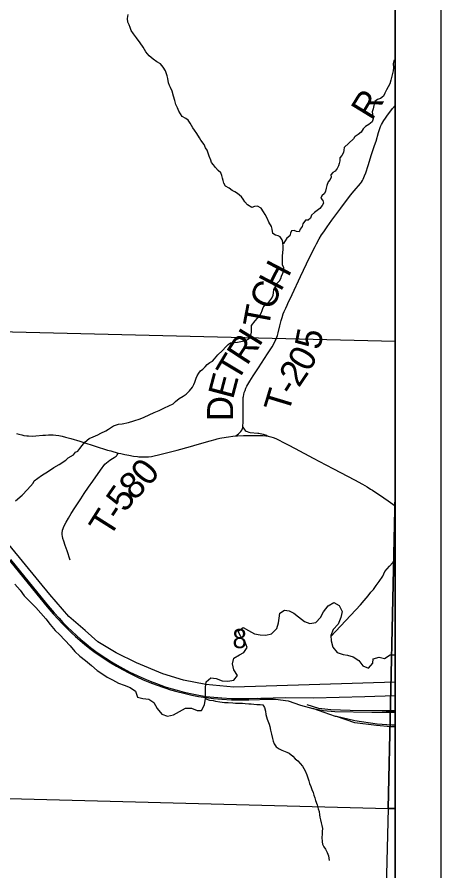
# Model space of a CAD drawing. Extents: x -19.9 to 41.9, y 0 to 32.3.
# Drawn here: x 8.077 to 9, y 15.733 to 17.59 of the extents above; entities that cross this region are included whole.
import ezdxf

# ---------------------------------------------------------------- set-up
doc = ezdxf.new("R2010")
doc.units = 0
for name, color, linetype in [('GM_X_Corporation', 7, 'Continuous'), ('GM_X_Major_River', 7, 'Continuous'), ('GM_X_Minor_River', 7, 'Continuous'), ('GM_X_Rail_Line', 7, 'Continuous'), ('GM_X_Section_Text', 7, 'Continuous'), ('GM_X_State_Route', 7, 'Continuous'), ('GM_X_Township_Road', 7, 'Continuous'), ('GM_X_Township_Road_Text', 7, 'Continuous'), ('SH_Data', 7, 'Continuous')]:
    doc.layers.add(name, color=color, linetype=linetype)

msp = doc.modelspace()

# ---------------------------------------------------------------- linework, layer by layer
at = {"layer": 'GM_X_Corporation'}
for points in [[(2.1, 17.918), (2.1, 14.1), (8.9, 14.1), (8.9, 17.8974), (7.9072, 17.9171), (7.5529, 17.9242), (7.3858, 17.9277), (6.9468, 17.937), (6.7, 17.9422), (6.3069, 17.9505), (6.2497, 17.9517), (6.2397, 17.9517), (5.9048, 17.9534), (5.761, 17.9543), (5.4954, 17.9559), (5.0257, 17.9637), (5.0192, 17.8403), (4.9169, 17.8392), (4.2613, 17.8672), (3.984, 17.879), (3.7505, 17.884), (2.973, 17.9007), (2.4715, 17.9106)], [(7.8246, 14.1), (8.9, 14.1), (8.9, 17.8974), (7.9072, 17.9171), (7.9012, 17.4524), (7.8776, 16.5173), (7.8702, 16.1679), (7.854, 15.4058), (7.8518, 15.3043)], [(8.9, 16.5515), (8.9, 16.8843), (7.8883, 16.9088), (7.8659, 15.8953), (8.8854, 15.8688)], [(8.9, 15.8686), (8.9, 16.5515), (8.8854, 15.8688)], [(8.8854, 15.8688), (8.8595, 14.8618), (7.8436, 14.8739), (7.8659, 15.8953)], [(8.9, 14.861), (8.9, 15.8686), (8.8854, 15.8688), (8.8595, 14.8618)]]:
    msp.add_lwpolyline(points, close=True, dxfattribs=at)
at = {"layer": 'GM_X_Major_River'}
for points in [[(8.0725, 16.3563), (8.0837, 16.3435), (8.093, 16.3311), (8.1057, 16.3184), (8.118, 16.306), (8.1291, 16.2933), (8.1399, 16.2809), (8.1496, 16.2692), (8.16, 16.2561), (8.1696, 16.2471), (8.1815, 16.2351), (8.1927, 16.2227), (8.2031, 16.21), (8.2142, 16.2002), (8.2261, 16.1909), (8.2391, 16.1801), (8.2518, 16.1692), (8.2637, 16.161), (8.2736, 16.1547), (8.2847, 16.1488), (8.2977, 16.1413), (8.3103, 16.1373), (8.3237, 16.1322), (8.3348, 16.124), (8.3391, 16.1108), (8.3509, 16.1079), (8.3639, 16.1069), (8.3753, 16.0991), (8.3823, 16.0859), (8.392, 16.0739), (8.4049, 16.0699), (8.4178, 16.0723), (8.4306, 16.0797), (8.4438, 16.087), (8.4568, 16.0872), (8.4694, 16.082), (8.4788, 16.0818), (8.4855, 16.0944), (8.4876, 16.108), (8.4871, 16.1183), (8.4877, 16.1316), (8.4891, 16.1445), (8.4989, 16.1526), (8.5103, 16.1516), (8.5236, 16.1464), (8.5358, 16.1454), (8.5494, 16.1475), (8.5573, 16.1578), (8.5491, 16.1706), (8.546, 16.1831), (8.5492, 16.196), (8.5613, 16.2026), (8.5711, 16.2077), (8.5778, 16.2188), (8.5739, 16.2305), (8.5646, 16.2421), (8.5588, 16.2542), (8.5693, 16.2627), (8.5808, 16.256), (8.5941, 16.2486), (8.6067, 16.2464), (8.6185, 16.2458), (8.631, 16.2483), (8.643, 16.2605), (8.6463, 16.2723), (8.648, 16.283), (8.649, 16.2932), (8.6596, 16.2998), (8.6699, 16.2984), (8.6794, 16.2932), (8.6898, 16.2854), (8.7028, 16.2753), (8.7146, 16.2713), (8.7279, 16.2733), (8.7376, 16.2841), (8.7443, 16.2963), (8.7544, 16.3093), (8.7665, 16.3171), (8.7787, 16.3104), (8.7846, 16.2972), (8.7817, 16.2839), (8.7762, 16.2698), (8.7653, 16.2583), (8.7605, 16.2449), (8.7607, 16.2332), (8.7646, 16.2199), (8.7739, 16.2079), (8.7868, 16.2035), (8.7964, 16.2021), (8.8086, 16.1989), (8.8209, 16.1905)], [(8.8209, 16.1905), (8.83, 16.1788), (8.8422, 16.1741), (8.8515, 16.1845), (8.8525, 16.194), (8.8653, 16.1976), (8.8771, 16.1948), (8.8891, 16.2026), (8.9, 16.2033)]]:
    msp.add_lwpolyline(points, dxfattribs=at)
at = {"layer": 'GM_X_Minor_River'}
for points in [[(8.4498, 17.3657), (8.4444, 17.3695), (8.4364, 17.3739), (8.4329, 17.3792), (8.4294, 17.3852), (8.4263, 17.3924), (8.4228, 17.4), (8.4208, 17.4083), (8.418, 17.4178), (8.4148, 17.4288), (8.4109, 17.4364), (8.4089, 17.4413), (8.407, 17.4466), (8.4053, 17.4561), (8.4037, 17.4621), (8.4002, 17.4728), (8.3955, 17.4811), (8.3893, 17.4878), (8.3817, 17.4927), (8.3737, 17.4983), (8.3645, 17.5054), (8.3575, 17.514), (8.3517, 17.5242), (8.3455, 17.5336), (8.337, 17.5446), (8.3309, 17.5536), (8.3258, 17.5604), (8.3235, 17.5668), (8.3211, 17.5729), (8.3184, 17.5789), (8.3179, 17.5866), (8.3193, 17.5957)], [(8.9, 17.4965), (8.8977, 17.4949), (8.8962, 17.4888), (8.8965, 17.4797), (8.8957, 17.4732), (8.8946, 17.4671), (8.893, 17.4611), (8.8907, 17.4523), (8.8884, 17.4447), (8.8815, 17.4318), (8.878, 17.4242), (8.8746, 17.4174), (8.8681, 17.4129), (8.862, 17.4106), (8.8563, 17.4064), (8.854, 17.3977), (8.8525, 17.3901), (8.8502, 17.384), (8.8516, 17.3741), (8.8524, 17.3684), (8.8504, 17.362), (8.8432, 17.3563), (8.836, 17.3521), (8.8306, 17.3464), (8.8264, 17.3396), (8.82, 17.3343), (8.8131, 17.3302), (8.813, 17.3299)], [(8.4621, 16.7905), (8.464, 16.7959), (8.4672, 16.8043), (8.4694, 16.8093), (8.4728, 16.8151), (8.4765, 16.8208), (8.4814, 16.824), (8.4866, 16.829), (8.4914, 16.834), (8.497, 16.8383), (8.5027, 16.8418), (8.5068, 16.8468), (8.5142, 16.8553), (8.5247, 16.8646), (8.5318, 16.8727), (8.5366, 16.8777), (8.5422, 16.8816), (8.5475, 16.8821), (8.5574, 16.8826), (8.5679, 16.8847), (8.574, 16.8863), (8.5792, 16.8887), (8.5845, 16.8933), (8.5859, 16.8983), (8.5873, 16.9044), (8.5876, 16.9131), (8.5875, 16.9189), (8.5957, 16.9289), (8.6005, 16.935), (8.6054, 16.9408), (8.6083, 16.9462), (8.6105, 16.952), (8.6127, 16.9581), (8.6172, 16.9639), (8.625, 16.9701), (8.6317, 16.9785), (8.6347, 16.9847), (8.6357, 16.9904), (8.6364, 16.9973), (8.6404, 17.0046), (8.643, 17.0103), (8.6486, 17.0165), (8.6515, 17.0215), (8.653, 17.0265), (8.6559, 17.033), (8.6577, 17.0387), (8.658, 17.0444), (8.6553, 17.0513), (8.6552, 17.0592), (8.6547, 17.0642), (8.6554, 17.0695), (8.6563, 17.0852), (8.6562, 17.0901), (8.6557, 17.1), (8.6545, 17.1057), (8.6503, 17.1117), (8.6453, 17.1139), (8.6396, 17.1157), (8.6339, 17.1191), (8.6326, 17.1282), (8.6314, 17.1343), (8.6256, 17.1441), (8.6217, 17.1524), (8.617, 17.1607), (8.6135, 17.1664), (8.6085, 17.1739), (8.6008, 17.1787), (8.5944, 17.1775), (8.5884, 17.1755), (8.5792, 17.1815), (8.5727, 17.1882), (8.5692, 17.1939), (8.5661, 17.1992), (8.5569, 17.2059), (8.5512, 17.2096), (8.5458, 17.2126), (8.5393, 17.2178), (8.5309, 17.2219), (8.5274, 17.2287), (8.5258, 17.2343), (8.5242, 17.2393), (8.523, 17.2453), (8.5207, 17.2514), (8.5149, 17.2563), (8.5091, 17.2623), (8.5045, 17.2683), (8.5003, 17.2736), (8.4987, 17.2785), (8.4952, 17.2876), (8.4932, 17.2936), (8.4908, 17.3001), (8.4877, 17.3057), (8.4842, 17.3125), (8.4773, 17.322), (8.4745, 17.3273), (8.4687, 17.3363), (8.4633, 17.3435), (8.4595, 17.3487), (8.4571, 17.354), (8.4544, 17.3593), (8.4498, 17.3657)], [(8.8127, 17.33), (8.8094, 17.3253), (8.7895, 17.3062), (8.7884, 17.3004), (8.7877, 17.2951), (8.7844, 17.2886), (8.7796, 17.2839), (8.7797, 17.2771), (8.7782, 17.2717), (8.7768, 17.266), (8.7738, 17.2602), (8.7698, 17.2544), (8.7645, 17.2517), (8.76, 17.2467), (8.7609, 17.2414), (8.759, 17.2364), (8.7546, 17.2314), (8.7513, 17.2237), (8.7498, 17.218), (8.7484, 17.2111), (8.7462, 17.2061), (8.7406, 17.2007), (8.7388, 17.1957), (8.7426, 17.1908), (8.7446, 17.1848), (8.7417, 17.1798), (8.7361, 17.1736), (8.7305, 17.1693), (8.7245, 17.165), (8.7181, 17.1588), (8.7163, 17.1523), (8.7107, 17.1481), (8.705, 17.148), (8.6991, 17.1399), (8.6976, 17.1345), (8.6932, 17.1284), (8.6917, 17.1226), (8.6853, 17.1237), (8.6803, 17.1255), (8.675, 17.125), (8.6725, 17.1201), (8.6707, 17.1143), (8.6643, 17.1089), (8.6606, 17.1031), (8.6573, 17.0977), (8.6559, 17.0967)], [(8.0739, 16.5379), (8.0881, 16.5499), (8.0997, 16.5627), (8.1124, 16.5762), (8.1142, 16.5812), (8.1307, 16.5928), (8.1453, 16.6026), (8.1573, 16.61), (8.1689, 16.617), (8.1836, 16.626), (8.1881, 16.631), (8.1997, 16.6377), (8.2045, 16.6435), (8.2094, 16.6458), (8.2139, 16.6516), (8.2191, 16.6582), (8.225, 16.6655), (8.2344, 16.6732), (8.243, 16.6772), (8.2483, 16.6792), (8.2532, 16.6815), (8.2596, 16.685), (8.2701, 16.6898), (8.2761, 16.694), (8.287, 16.7007), (8.2983, 16.7043), (8.3063, 16.7052), (8.3198, 16.7084), (8.3315, 16.7116), (8.3455, 16.7164), (8.3537, 16.72), (8.3647, 16.7247), (8.3756, 16.7298), (8.3865, 16.7346), (8.3985, 16.7401), (8.4075, 16.7444), (8.4169, 16.7491), (8.4222, 16.7541), (8.4304, 16.7607), (8.439, 16.7654), (8.445, 16.7697), (8.4525, 16.7771), (8.4592, 16.7848), (8.4621, 16.7905)], [(8.7605, 16.2431), (8.8252, 16.3117), (8.8332, 16.3212), (8.8413, 16.3314), (8.8474, 16.339), (8.8531, 16.3451), (8.8592, 16.3534), (8.8653, 16.3625), (8.8733, 16.3739), (8.8779, 16.3838), (8.8878, 16.3959), (8.8951, 16.4038), (8.8989, 16.411), (8.9, 16.4117)], [(8.4876, 16.108), (8.488, 16.1073), (8.4959, 16.1047), (8.5039, 16.1037), (8.5089, 16.1023), (8.5187, 16.1009), (8.529, 16.0995), (8.5365, 16.0993), (8.5471, 16.0983), (8.5525, 16.098), (8.5581, 16.0981), (8.568, 16.0975), (8.5737, 16.0968), (8.5816, 16.0961), (8.5869, 16.0962), (8.593, 16.0959), (8.5991, 16.0953), (8.6066, 16.095), (8.6123, 16.0939), (8.6158, 16.0887), (8.6178, 16.0803), (8.6191, 16.0731), (8.6219, 16.0633), (8.6258, 16.0523), (8.6274, 16.047), (8.629, 16.039), (8.6311, 16.0303), (8.6331, 16.0212), (8.6347, 16.0151), (8.637, 16.0091), (8.6413, 16.003), (8.6478, 15.9982), (8.6539, 15.9956), (8.6646, 15.9912), (8.6695, 15.989), (8.6772, 15.9827), (8.6826, 15.977), (8.6887, 15.9722), (8.6933, 15.9669), (8.6987, 15.9605), (8.7042, 15.9507), (8.7077, 15.942), (8.7101, 15.9352), (8.7124, 15.9288), (8.714, 15.9235), (8.7168, 15.9163), (8.7188, 15.9102), (8.7215, 15.9038), (8.7231, 15.8981), (8.7251, 15.892), (8.7267, 15.8864), (8.7306, 15.8765), (8.733, 15.8678), (8.7346, 15.8625), (8.7355, 15.8553), (8.7363, 15.8503), (8.7379, 15.8439), (8.7395, 15.8378), (8.7407, 15.8318), (8.742, 15.8253), (8.7417, 15.8185), (8.7414, 15.8124), (8.7407, 15.8063), (8.7416, 15.7964), (8.7424, 15.7914), (8.7452, 15.7858), (8.749, 15.7801), (8.7522, 15.7729), (8.7549, 15.7657), (8.7558, 15.7608), (8.7566, 15.7555)]]:
    msp.add_lwpolyline(points, dxfattribs=at)
at = {"layer": 'GM_X_Rail_Line'}
for p, q in [((8.6011, 16.1085), (8.6288, 16.1069)), ((8.8627, 16.0784), (8.8987, 16.0813)), ((8.9, 16.0813), (8.8987, 16.0813)), ((8.8627, 16.0784), (8.9, 16.0782))]:
    msp.add_line(p, q, dxfattribs=at)
for points in [[(8.9, 16.1433), (8.5494, 16.1329), (8.4881, 16.1385), (8.4395, 16.1476), (8.3942, 16.1617), (8.3374, 16.1854), (8.2929, 16.2072), (8.2531, 16.2309), (8.2252, 16.2556), (8.1896, 16.2862), (8.1483, 16.3345), (7.9464, 16.5797)], [(8.0607, 16.4081), (8.1204, 16.3349), (8.143, 16.3076), (8.156, 16.2924), (8.1665, 16.2806), (8.175, 16.2715), (8.1846, 16.2615), (8.1952, 16.2514), (8.2045, 16.243), (8.2145, 16.2341), (8.2249, 16.2253), (8.2357, 16.2169), (8.2472, 16.2082), (8.2578, 16.201), (8.2687, 16.1934), (8.2811, 16.1856), (8.2936, 16.1782), (8.3066, 16.1707), (8.3217, 16.1628), (8.3376, 16.1552), (8.352, 16.1486), (8.3659, 16.1429), (8.3798, 16.1376), (8.3988, 16.131), (8.411, 16.1271), (8.425, 16.1233), (8.4401, 16.1193), (8.4579, 16.1153), (8.4725, 16.1126), (8.4888, 16.1099), (8.5051, 16.1081), (8.523, 16.1066), (8.5438, 16.1053), (8.5622, 16.1049), (8.5817, 16.1051), (8.6288, 16.1069)], [(8.0629, 16.4099), (8.1226, 16.3367), (8.1452, 16.3094), (8.1582, 16.2942), (8.1686, 16.2825), (8.177, 16.2734), (8.1866, 16.2635), (8.1972, 16.2535), (8.2064, 16.2451), (8.2163, 16.2362), (8.2267, 16.2275), (8.2374, 16.2191), (8.2488, 16.2105), (8.2594, 16.2033), (8.2702, 16.1958), (8.2826, 16.188), (8.295, 16.1806), (8.3079, 16.1732), (8.3229, 16.1653), (8.3388, 16.1578), (8.3531, 16.1512), (8.367, 16.1455), (8.3808, 16.1403), (8.3997, 16.1337), (8.4118, 16.1299), (8.4258, 16.126), (8.4408, 16.1221), (8.4585, 16.1181), (8.473, 16.1154), (8.4892, 16.1127), (8.5053, 16.1109), (8.5232, 16.1094), (8.5439, 16.1081), (8.5622, 16.1077), (8.5816, 16.108), (8.6608, 16.1102), (8.7229, 16.1091), (8.8341, 16.1123), (8.9, 16.1143)], [(8.6288, 16.1069), (8.6398, 16.1063), (8.6674, 16.1027), (8.6944, 16.0938), (8.7208, 16.0863)], [(8.8987, 16.0813), (8.8027, 16.0818), (8.76, 16.0831), (8.7344, 16.0865), (8.7089, 16.0943)], [(8.7724, 16.0685), (8.7704, 16.0689), (8.7208, 16.0863)], [(8.7208, 16.0863), (8.744, 16.0819), (8.7691, 16.0797), (8.8494, 16.0785), (8.8627, 16.0784)], [(8.9, 16.0464), (8.8909, 16.0465), (8.8598, 16.049), (8.8123, 16.0553), (8.7724, 16.0685)], [(8.9, 16.0502), (8.8931, 16.0503), (8.861, 16.0523), (8.8127, 16.0596), (8.7724, 16.0685)]]:
    msp.add_lwpolyline(points, dxfattribs=at)
at = {"layer": 'GM_X_State_Route'}
for points in [[(8.076, 16.6842), (8.0809, 16.6827), (8.0876, 16.681), (8.092, 16.6801), (8.0982, 16.6791), (8.1024, 16.6788), (8.1098, 16.6787), (8.1177, 16.6792), (8.1335, 16.6805), (8.1394, 16.6809), (8.1454, 16.6811), (8.1498, 16.6812), (8.1561, 16.681), (8.1618, 16.6805), (8.1682, 16.6796), (8.1757, 16.6782), (8.1827, 16.6766), (8.1944, 16.6735), (8.2137, 16.6678), (8.2207, 16.6657), (8.2741, 16.6483), (8.281, 16.6463), (8.2974, 16.6418), (8.3031, 16.6405), (8.312, 16.6384), (8.3202, 16.6369), (8.331, 16.6353), (8.3394, 16.634), (8.3426, 16.6337), (8.3482, 16.6335), (8.3556, 16.6334), (8.3631, 16.6336), (8.3701, 16.6345), (8.3759, 16.6354), (8.385, 16.6375), (8.3938, 16.6399), (8.4255, 16.648), (8.4551, 16.6563), (8.4696, 16.6601), (8.4977, 16.6682), (8.5083, 16.6713), (8.513, 16.6725), (8.5188, 16.6739), (8.5322, 16.6765), (8.5376, 16.6773), (8.5466, 16.6783), (8.5534, 16.6789), (8.5572, 16.6793), (8.5702, 16.6799), (8.5924, 16.6802), (8.6059, 16.68), (8.6131, 16.6796), (8.6187, 16.6789), (8.624, 16.6781)], [(8.624, 16.6781), (8.6265, 16.6777), (8.63, 16.6768), (8.6348, 16.6753), (8.6405, 16.6732), (8.6447, 16.6713), (8.6586, 16.6642), (8.6672, 16.6597), (8.6827, 16.6516), (8.7221, 16.6305), (8.7494, 16.6159), (8.7658, 16.6074), (8.8118, 16.5832), (8.829, 16.574), (8.8396, 16.5679), (8.8468, 16.5633), (8.8507, 16.5608), (8.8558, 16.5574), (8.866, 16.5507), (8.8851, 16.5375), (8.9, 16.5272)]]:
    msp.add_lwpolyline(points, dxfattribs=at)
at = {"layer": 'GM_X_Township_Road'}
for points in [[(8.5534, 16.6789), (8.5564, 16.6812), (8.5592, 16.6837), (8.562, 16.6862), (8.5642, 16.6885), (8.5664, 16.6913), (8.5673, 16.6931), (8.5678, 16.6949), (8.5686, 16.6983), (8.5688, 16.7028), (8.5691, 16.7058), (8.5694, 16.7172), (8.5697, 16.7303), (8.5694, 16.746), (8.5693, 16.7549), (8.5694, 16.7597), (8.5696, 16.7625), (8.5698, 16.765), (8.5707, 16.769), (8.5719, 16.7732), (8.5735, 16.7776), (8.5753, 16.7826), (8.5774, 16.7871), (8.5836, 16.7981), (8.5873, 16.8037), (8.5913, 16.8098), (8.6028, 16.8271), (8.6227, 16.8572), (8.6256, 16.8618), (8.6322, 16.8729), (8.6352, 16.8775), (8.6393, 16.8859), (8.6411, 16.8892), (8.6428, 16.8939), (8.6439, 16.8976), (8.6454, 16.903), (8.6492, 16.9186), (8.6521, 16.9298), (8.654, 16.9367), (8.6568, 16.9444), (8.6588, 16.9494), (8.662, 16.9567), (8.665, 16.963), (8.6669, 16.9668), (8.6763, 16.9867), (8.6942, 17.0256), (8.7074, 17.0535), (8.7167, 17.0727), (8.7259, 17.0909), (8.7291, 17.0969), (8.7349, 17.1074), (8.7402, 17.1159), (8.7448, 17.1231), (8.7523, 17.1337), (8.7627, 17.148), (8.7818, 17.1739), (8.8031, 17.2026), (8.8109, 17.2117), (8.8251, 17.2276), (8.8272, 17.2307), (8.8293, 17.2342), (8.8308, 17.2372), (8.8323, 17.2408), (8.8339, 17.2446), (8.8362, 17.2513), (8.8417, 17.2671), (8.8491, 17.2907), (8.8556, 17.3102), (8.8587, 17.3198), (8.8644, 17.3384), (8.8663, 17.345), (8.8683, 17.3517), (8.8704, 17.3561), (8.8757, 17.365), (8.8792, 17.3701), (8.8837, 17.3762), (8.8867, 17.38), (8.8947, 17.3906), (8.9, 17.3973)], [(8.5686, 16.6983), (8.5699, 16.6957), (8.5714, 16.6933), (8.5736, 16.6911), (8.5759, 16.6896), (8.5779, 16.6886), (8.582, 16.6873), (8.5848, 16.6866), (8.6011, 16.6853), (8.6033, 16.685), (8.6129, 16.683), (8.6152, 16.6823), (8.6176, 16.6815), (8.6203, 16.6803), (8.6219, 16.6794), (8.624, 16.6781)], [(8.193, 16.4089), (8.1859, 16.4288), (8.1818, 16.4404), (8.1788, 16.4499), (8.1771, 16.4562), (8.176, 16.4607), (8.1755, 16.464), (8.1752, 16.4676), (8.1758, 16.4739), (8.1774, 16.478), (8.1791, 16.4823), (8.1844, 16.4917), (8.1891, 16.4999), (8.195, 16.5101), (8.2032, 16.5229), (8.2159, 16.5425), (8.2235, 16.5537), (8.2329, 16.5672), (8.2425, 16.5805), (8.2586, 16.6043), (8.2686, 16.6172), (8.2721, 16.6208), (8.2753, 16.6237), (8.2795, 16.6265), (8.2848, 16.6297), (8.2888, 16.6321), (8.2926, 16.6351), (8.2941, 16.6366), (8.2949, 16.6377), (8.2974, 16.6418)]]:
    msp.add_lwpolyline(points, dxfattribs=at)
at = {"layer": 'SH_Data'}
for p, q in [((9, 21), (9, 14)), ((8.9, 20.9), (8.9, 14.1))]:
    msp.add_line(p, q, dxfattribs=at)

# ---------------------------------------------------------------- texts
at = {"layer": 'GM_X_Section_Text'}
msp.add_text('8', height=0.0419, rotation=0, dxfattribs=at).set_placement((8.5462, 16.2175))
at = {"layer": 'GM_X_Township_Road_Text'}
for s, rotation, p in [('R', 58.5556, (8.8496, 17.3626)), ('H', 62.5633, (8.6514, 16.9911)), ('C', 64.0371, (8.6311, 16.9495)), ('T', 79.3161, (8.6245, 16.9115)), ('R', 56.9702, (8.5779, 16.8302)), ('I', 58.4119, (8.6042, 16.8707)), ('5', 78.6219, (8.7365, 16.8644)), ('T', 59.2185, (8.5565, 16.7942)), ('0', 61.0799, (8.713, 16.816)), ('2', 56.0718, (8.6907, 16.7824)), ('E', 75.2185, (8.5472, 16.757)), ('T', 73.2187, (8.6679, 16.7259)), ('-', 57.8862, (8.6785, 16.763)), ('D', 89.8907, (8.5476, 16.7108)), ('0', 50.5639, (8.3638, 16.567)), ('8', 41.9002, (8.3312, 16.5369)), ('5', 55.2245, (8.3136, 16.5107)), ('T', 57.7852, (8.2785, 16.4558)), ('-', 56.8122, (8.301, 16.4916))]:
    msp.add_text(s, height=0.0568, rotation=rotation, dxfattribs=at).set_placement(p)

doc.saveas('drawing.dxf')
